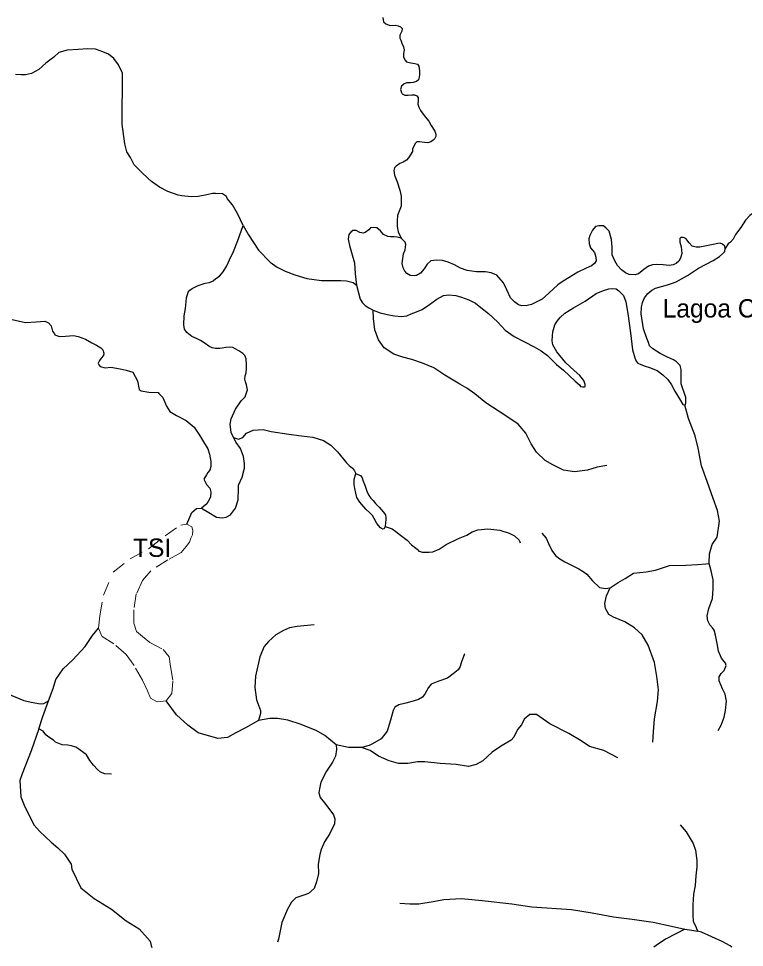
# Model space of a CAD drawing. Extents: x 436.3 to 500.4, y 8231 to 8286.4.
# Drawn here: x 489.18 to 495.5, y 8231.04 to 8239.13 of the extents above; entities that cross this region are included whole.
import ezdxf
from ezdxf.enums import TextEntityAlignment as Align

# ---------------------------------------------------------------- set-up
doc = ezdxf.new("R2010")
doc.units = 0
doc.header["$LTSCALE"] = 0.08
doc.linetypes.add('LONG_DASHED', pattern=[7.5, 6, -1.5])
doc.linetypes.add('SHORT_DASHED', pattern=[2.7, 1.5, -1.2])
for name, color, linetype, lineweight in [('2', 7, 'Continuous', 25), ('21', 7, 'SHORT_DASHED', 13), ('9', 7, 'LONG_DASHED', 25)]:
    doc.layers.add(name, color=color, linetype=linetype, lineweight=lineweight)
doc.layers.add('61', color=7, linetype='Continuous')

msp = doc.modelspace()

# ---------------------------------------------------------------- linework, layer by layer
at = {"layer": '2'}
for points in [[(495.3302, 8237.1297), (495.3276, 8237.1503), (495.3068, 8237.1684), (495.2886, 8237.1762), (495.2678, 8237.1737), (495.2262, 8237.1634), (495.1118, 8237.1405), (495.078, 8237.1405), (495.0442, 8237.1508), (495.0182, 8237.1793), (494.9897, 8237.2154), (494.9663, 8237.2258), (494.9455, 8237.2259), (494.9377, 8237.2155), (494.9376, 8237.1846), (494.948, 8237.1434), (494.9531, 8237.0866), (494.9427, 8237.0453), (494.927, 8237.0196), (494.9062, 8236.9989), (494.8777, 8236.9862), (494.8438, 8236.9811), (494.7918, 8236.9864), (494.7347, 8236.9891), (494.6983, 8236.9866), (494.6644, 8236.9763), (494.6228, 8236.9454), (494.5773, 8236.9074), (494.5488, 8236.8997), (494.4968, 8236.9024), (494.463, 8236.9179), (494.4293, 8236.9438), (494.3955, 8236.9826), (494.3696, 8237.0213), (494.3488, 8237.0755), (494.3463, 8237.1401), (494.3412, 8237.2072), (494.3205, 8237.2795), (494.2946, 8237.3053), (494.2713, 8237.326), (494.2323, 8237.3261), (494.2036, 8237.321), (494.1776, 8237.2902), (494.1542, 8237.2437), (494.1438, 8237.2128), (494.1463, 8237.1716), (494.1592, 8237.1345), (494.1929, 8237.0958), (494.2059, 8237.0545), (494.2084, 8237.021), (494.1928, 8236.9978), (494.1668, 8236.9797), (494.1225, 8236.9593), (494.0498, 8236.9232), (493.9744, 8236.877), (493.9198, 8236.8436), (493.8755, 8236.8127), (493.7975, 8236.7407), (493.7377, 8236.6892), (493.6792, 8236.6583), (493.6453, 8236.6429), (493.609, 8236.6326), (493.5622, 8236.6301), (493.5311, 8236.6379), (493.4973, 8236.6639), (493.4637, 8236.7), (493.43, 8236.7698), (493.4015, 8236.8293)], [(492.1181, 8237.2875), (492.091, 8237.286), (492.0728, 8237.2731), (492.0546, 8237.2524), (492.0494, 8237.2112), (492.0622, 8237.1544), (492.0853, 8237.0744), (492.1033, 8237.0047), (492.1109, 8236.9092), (492.1222, 8236.811)], [(492.5112, 8237.2181), (492.4749, 8237.2285), (492.4491, 8237.2311), (492.4179, 8237.2311), (492.3946, 8237.2337), (492.3557, 8237.2518), (492.3298, 8237.2828), (492.2988, 8237.3086), (492.2677, 8237.3138), (492.2443, 8237.3086), (492.2287, 8237.2907), (492.1975, 8237.2674), (492.1803, 8237.262), (492.1509, 8237.2674), (492.1181, 8237.2875)], [(493.027, 8236.9593), (492.9752, 8236.9877), (492.9207, 8237.0111), (492.8714, 8237.0241), (492.8144, 8237.0268), (492.7702, 8237.0217), (492.7364, 8236.9933), (492.7105, 8236.952), (492.6792, 8236.916), (492.6454, 8236.8953), (492.6377, 8236.8953), (492.6247, 8236.8902), (492.5884, 8236.8954), (492.5599, 8236.9109), (492.5418, 8236.9316), (492.5288, 8236.96), (492.5185, 8236.9987), (492.5264, 8237.0426), (492.5317, 8237.0839), (492.5448, 8237.1174), (492.5526, 8237.1639), (492.5449, 8237.1846), (492.5112, 8237.2181)], [(494.908, 8236.1408), (494.882, 8236.1589), (494.83, 8236.1823), (494.7651, 8236.2159), (494.7027, 8236.2548), (494.6741, 8236.2828), (494.6637, 8236.3112), (494.6455, 8236.3552), (494.6194, 8236.4311), (494.6014, 8236.5602), (494.604, 8236.617), (494.6118, 8236.6582), (494.6301, 8236.6994), (494.6587, 8236.738), (494.6925, 8236.7664), (494.7263, 8236.7843), (494.7784, 8236.7997), (494.8303, 8236.8125), (494.8642, 8236.8254), (494.9058, 8236.8381), (494.9526, 8236.8665), (495.0046, 8236.8947), (495.0986, 8236.9573), (495.2261, 8237.0242), (495.2833, 8237.0601), (495.3119, 8237.0859), (495.3275, 8237.1039), (495.3302, 8237.1297)], [(493.4015, 8236.8293), (493.3445, 8236.8964), (493.2952, 8236.9172), (493.2458, 8236.925), (493.168, 8236.9252), (493.0867, 8236.9385), (493.027, 8236.9593)], [(492.1222, 8236.811), (492.1546, 8236.6893), (492.1753, 8236.6557), (492.1986, 8236.6325), (492.2302, 8236.6135), (492.2662, 8236.5923)], [(492.2662, 8236.5923), (492.3286, 8236.5696), (492.4038, 8236.5514), (492.4531, 8236.5436), (492.5128, 8236.5384), (492.5594, 8236.5435), (492.5984, 8236.559), (492.6452, 8236.577), (492.6945, 8236.5976), (492.7569, 8236.6414), (492.8218, 8236.6878), (492.879, 8236.7187), (492.9257, 8236.7263), (492.988, 8236.7211), (493.0373, 8236.7055), (493.1002, 8236.6822), (493.1572, 8236.6537), (493.204, 8236.6149), (493.2714, 8236.5631), (493.3518, 8236.4881), (493.4166, 8236.4182), (493.4946, 8236.3639), (493.5838, 8236.3162), (493.6694, 8236.2722), (493.7292, 8236.2385), (493.7837, 8236.197), (493.8642, 8236.1195), (493.9239, 8236.0703), (494.0255, 8235.9749), (494.0619, 8235.9412), (494.0723, 8235.9283), (494.0905, 8235.9257), (494.1061, 8235.9256), (494.1139, 8235.9282), (494.1139, 8235.9437), (494.1009, 8235.9799), (494.0671, 8236.0239), (494.0177, 8236.0653), (493.9451, 8236.1326), (493.8672, 8236.2283), (493.8309, 8236.2903), (493.8257, 8236.3265), (493.8283, 8236.3677), (493.831, 8236.4039), (493.8492, 8236.4632), (493.8675, 8236.4968), (493.896, 8236.5276), (493.9352, 8236.5668), (494.0106, 8236.6131), (494.112, 8236.6697), (494.2083, 8236.7366), (494.2732, 8236.7647), (494.3174, 8236.7776), (494.3513, 8236.7801), (494.3824, 8236.7774), (494.4058, 8236.7619), (494.4473, 8236.7205), (494.4655, 8236.6663), (494.4836, 8236.563), (494.5075, 8236.3946), (494.5256, 8236.2475), (494.5437, 8236.1778), (494.5567, 8236.1493), (494.5723, 8236.1312), (494.5983, 8236.1183), (494.6346, 8236.1053), (494.6736, 8236.0923), (494.7391, 8236.0657), (494.7884, 8236.0294), (494.8326, 8235.988), (494.8638, 8235.9415), (494.8924, 8235.8872), (494.9417, 8235.8045), (494.9621, 8235.77), (494.9807, 8235.764)], [(494.9599, 8235.9162), (494.947, 8235.9497), (494.947, 8235.9781), (494.947, 8236.0246), (494.9496, 8236.0762), (494.9393, 8236.1098), (494.908, 8236.1408)], [(494.9807, 8235.764), (494.9859, 8235.7683), (494.9885, 8235.789), (494.9886, 8235.8303), (494.9755, 8235.8748), (494.9599, 8235.9162)], [(492.3715, 8234.7091), (492.3626, 8234.6884), (492.3477, 8234.6854), (492.3314, 8234.6957), (492.2987, 8234.7343), (492.2763, 8234.7772), (492.2614, 8234.8025), (492.2376, 8234.8277), (492.2035, 8234.8603), (492.1514, 8234.9196), (492.1246, 8234.9611), (492.1156, 8234.9982), (492.1082, 8235.0397), (492.1022, 8235.0738), (492.1021, 8235.1167), (492.1152, 8235.1691)], [(492.1142, 8235.1697), (492.1181, 8235.1672), (492.1571, 8235.1523), (492.1705, 8235.1331), (492.1794, 8235.1035), (492.1958, 8235.0679), (492.2121, 8235.0145), (492.2285, 8234.9775), (492.2463, 8234.9537), (492.2657, 8234.933), (492.288, 8234.9078), (492.3207, 8234.8751), (492.3549, 8234.8351), (492.3743, 8234.8099), (492.3787, 8234.7863), (492.3773, 8234.7669), (492.3744, 8234.7418), (492.3715, 8234.7091)]]:
    msp.add_lwpolyline(points, dxfattribs=at)
at = {"layer": '21'}
for points in [[(489.8759, 8233.8235), (489.8882, 8233.9299), (489.9196, 8234.1096), (490.0038, 8234.3107), (490.1516, 8234.4274), (490.31, 8234.5123), (490.4572, 8234.6269), (490.5918, 8234.7198), (490.6451, 8234.7283)], [(490.6451, 8234.7283), (490.6872, 8234.7061), (490.6985, 8234.6724), (490.6929, 8234.6359), (490.6789, 8234.605), (490.6678, 8234.5713), (490.6397, 8234.5348), (490.5955, 8234.4813), (490.4794, 8234.4176), (490.3315, 8234.3221), (490.2576, 8234.2374), (490.205, 8234.121), (490.1842, 8233.9834), (490.1844, 8233.8671), (490.2058, 8233.7932), (490.2587, 8233.751), (490.3223, 8233.6983), (490.4388, 8233.6351), (490.4918, 8233.5718), (490.5026, 8233.4872), (490.524, 8233.3603), (490.5137, 8233.2545), (490.4648, 8233.1901)], [(490.4648, 8233.1901), (490.3871, 8233.1802), (490.3284, 8233.2124), (490.3022, 8233.2752), (490.2597, 8233.3703), (490.1853, 8233.497), (490.1174, 8233.5926), (490.0085, 8233.6869), (489.9044, 8233.7528), (489.8759, 8233.8235)]]:
    msp.add_lwpolyline(points, dxfattribs=at)
at = {"layer": '9'}
msp.add_line((495.3908, 8231.043), (495.3753, 8231.0542), dxfattribs=at)
for points in [[(492.3509, 8239.142), (492.3572, 8239.1041), (492.3761, 8239.0872), (492.4162, 8239.0724), (492.4584, 8239.0744), (492.4837, 8239.0702), (492.5048, 8239.0617), (492.5196, 8239.0448), (492.5173, 8239.0217), (492.5089, 8239.0049), (492.5004, 8238.9881), (492.4982, 8238.9607), (492.5067, 8238.9438), (492.5171, 8238.9186), (492.5297, 8238.887), (492.536, 8238.8596), (492.5317, 8238.8238), (492.5316, 8238.7964), (492.5442, 8238.7712), (492.5569, 8238.7564), (492.5949, 8238.7458), (492.6286, 8238.7415), (492.6521, 8238.734), (492.6648, 8238.7172), (492.6711, 8238.6772), (492.671, 8238.6456), (492.6667, 8238.6204), (492.6624, 8238.5994), (492.6455, 8238.5846), (492.6139, 8238.5763), (492.5927, 8238.5721), (492.559, 8238.5721), (492.5357, 8238.5638), (492.5146, 8238.5449), (492.5061, 8238.5155), (492.5124, 8238.4881), (492.5208, 8238.4755), (492.5419, 8238.4649), (492.5714, 8238.4649), (492.6031, 8238.4669), (492.6263, 8238.4669), (492.6473, 8238.4585), (492.6579, 8238.4437), (492.6578, 8238.4184), (492.6557, 8238.3869), (492.664, 8238.3617), (492.6787, 8238.3301), (492.721, 8238.2766), (492.7505, 8238.2386), (492.7715, 8238.2008), (492.8031, 8238.1523), (492.8136, 8238.1251), (492.8114, 8238.1061), (492.8029, 8238.0872), (492.7881, 8238.0725)], [(491.1345, 8237.3301), (491.09, 8237.4274), (491.0415, 8237.5084), (490.9969, 8237.5651), (490.9888, 8237.5813), (490.9563, 8237.6056), (490.8953, 8237.6096), (490.8692, 8237.6077), (490.8204, 8237.5955), (490.7432, 8237.5832), (490.6821, 8237.579), (490.6008, 8237.587), (490.5683, 8237.5951), (490.4789, 8237.6273), (490.4059, 8237.6637), (490.3368, 8237.7123), (490.3085, 8237.7406), (490.2516, 8237.7933), (490.1868, 8237.8581), (490.1544, 8237.923), (490.1221, 8237.9716), (490.106, 8238.0406), (490.0822, 8238.2133), (490.0835, 8238.656), (490.0511, 8238.729), (490.0106, 8238.7858), (489.9619, 8238.8222), (489.9147, 8238.8421), (489.8493, 8238.8665), (489.7839, 8238.8685), (489.6981, 8238.8621), (489.6041, 8238.8578), (489.5304, 8238.8372), (489.4873, 8238.7964), (489.4177, 8238.7431), (489.3568, 8238.6881), (489.2932, 8238.6533), (489.24, 8238.643), (489.2012, 8238.6429), (489.1521, 8238.6448)], [(492.7881, 8238.0725), (492.7691, 8238.0578), (492.7437, 8238.0495), (492.7142, 8238.0537), (492.6695, 8238.0595), (492.6484, 8238.0575), (492.6336, 8238.0449)], [(492.6336, 8238.0449), (492.623, 8238.0239), (492.6103, 8237.9986), (492.6081, 8237.9735), (492.5742, 8237.9188), (492.5573, 8237.8978), (492.5276, 8237.881), (492.5003, 8237.8684), (492.4664, 8237.8454), (492.4516, 8237.8307), (492.4473, 8237.8076), (492.4535, 8237.7686), (492.4766, 8237.7097), (492.4997, 8237.6382), (492.5101, 8237.5857), (492.5122, 8237.5374), (492.5099, 8237.4975), (492.4993, 8237.4701), (492.4801, 8237.4176), (492.4758, 8237.3693), (492.4756, 8237.3219), (492.484, 8237.2756), (492.5112, 8237.2181)], [(496.4212, 8237.4803), (496.3951, 8237.5015), (496.3688, 8237.515), (496.3387, 8237.5228), (496.2928, 8237.5294), (496.191, 8237.5131), (496.1418, 8237.4969), (496.0991, 8237.4969), (496.0467, 8237.5002), (495.9942, 8237.5133), (495.9285, 8237.5101), (495.8597, 8237.507), (495.7707, 8237.5068), (495.7215, 8237.4971), (495.6493, 8237.481), (495.5967, 8237.4518), (495.5476, 8237.4161), (495.5082, 8237.3771), (495.4687, 8237.312), (495.4228, 8237.2503), (495.3997, 8237.2114), (495.3768, 8237.1854), (495.357, 8237.1691), (495.3302, 8237.1297)], [(491.0516, 8235.4842), (491.0296, 8235.5279), (491.0208, 8235.5979), (491.0296, 8235.646), (491.069, 8235.7292), (491.1171, 8235.8036), (491.1524, 8235.8365), (491.1611, 8235.8627), (491.1743, 8235.8977), (491.1655, 8235.9415), (491.1556, 8235.9676), (491.1496, 8235.9914), (491.1516, 8236.0211), (491.1616, 8236.047), (491.1656, 8236.0846), (491.1656, 8236.1204), (491.1617, 8236.168), (491.1498, 8236.1976), (491.1319, 8236.2155), (491.0962, 8236.2373), (491.0664, 8236.255), (491.0466, 8236.2668), (491.0188, 8236.2688), (490.985, 8236.2667), (490.9512, 8236.2608), (490.9313, 8236.2587), (490.8956, 8236.2586), (490.8657, 8236.2644), (490.8359, 8236.2783), (490.8041, 8236.302), (490.7645, 8236.3277), (490.7287, 8236.3455), (490.689, 8236.3632), (490.6454, 8236.3969), (490.6255, 8236.4265), (490.6181, 8236.4645), (490.6216, 8236.5425), (490.6319, 8236.607), (490.6388, 8236.6646), (490.6423, 8236.6985), (490.6559, 8236.7494), (490.6696, 8236.7664), (490.69, 8236.78), (490.7445, 8236.8072), (490.8056, 8236.8277), (490.843, 8236.8345), (490.8736, 8236.8482), (490.8975, 8236.8686), (490.9281, 8236.8889), (490.9621, 8236.9263), (490.9928, 8236.9773), (491.0168, 8237.0315), (491.0509, 8237.1028), (491.0885, 8237.1977), (491.1345, 8237.3301)], [(491.1345, 8237.3301), (491.1831, 8237.249), (491.2682, 8237.1153), (491.3696, 8237.0101), (491.4305, 8236.9655), (491.4995, 8236.9331), (491.5849, 8236.9007), (491.6906, 8236.8684), (491.8183, 8236.8514), (491.9851, 8236.8514), (492.0335, 8236.8478), (492.0924, 8236.8339), (492.1222, 8236.811)], [(494.3007, 8235.2397), (494.2171, 8235.2243), (494.1337, 8235.1985), (494.0189, 8235.1831), (493.925, 8235.1988), (493.8311, 8235.2456), (493.7633, 8235.2821), (493.6903, 8235.3549), (493.6433, 8235.4276), (493.5964, 8235.5211), (493.5285, 8235.5991), (493.4294, 8235.6667), (493.2469, 8235.7864), (493.153, 8235.8643), (493.0831, 8235.9118), (493.0205, 8235.9482), (492.8903, 8236.0262), (492.7965, 8236.0886), (492.6975, 8236.1302), (492.6037, 8236.1615), (492.5255, 8236.1823), (492.4474, 8236.2083), (492.3641, 8236.2654), (492.3122, 8236.3329), (492.2811, 8236.421), (492.2707, 8236.5196), (492.2662, 8236.5923)], [(489.1236, 8236.5124), (489.2156, 8236.4897), (489.2425, 8236.4859), (489.3345, 8236.49), (489.4089, 8236.4967), (489.4395, 8236.4815), (489.4625, 8236.4548), (489.474, 8236.4089), (489.4931, 8236.3861), (489.497, 8236.3784), (489.5353, 8236.3633), (489.5889, 8236.3672), (489.6579, 8236.3712), (489.7, 8236.3637), (489.7613, 8236.3409), (489.8187, 8236.3066), (489.857, 8236.2876), (489.8953, 8236.2648), (489.9144, 8236.2457), (489.9221, 8236.219), (489.9182, 8236.1961), (489.8991, 8236.173), (489.8837, 8236.1539), (489.8722, 8236.1309), (489.8799, 8236.1157), (489.8913, 8236.1004), (489.9334, 8236.089)], [(489.9334, 8236.089), (489.9833, 8236.0968), (490.0636, 8236.0818), (490.1173, 8236.0704), (490.1747, 8236.0515), (490.2142, 8235.9773), (490.2294, 8235.9009)], [(490.2294, 8235.9009), (490.2486, 8235.8895), (490.3137, 8235.8781), (490.3941, 8235.8745), (490.4018, 8235.8668), (490.4362, 8235.8325), (490.4669, 8235.7562), (490.4975, 8235.7103), (490.5549, 8235.6761), (490.6391, 8235.6304), (490.7081, 8235.5732), (490.7543, 8235.5033), (490.7888, 8235.4461), (490.8271, 8235.3849), (490.8425, 8235.3391), (490.854, 8235.274), (490.854, 8235.2319), (490.8464, 8235.1975), (490.8272, 8235.1783), (490.8158, 8235.1591), (490.7928, 8235.1208), (490.8159, 8235.0749), (490.8465, 8235.0406), (490.8542, 8235.0061), (490.8505, 8234.9639), (490.8314, 8234.9257), (490.8199, 8234.9065), (490.7712, 8234.8662)], [(495.1924, 8234.3869), (495.1961, 8234.471), (495.2176, 8234.5523), (495.2607, 8234.6164), (495.2822, 8234.7535), (495.265, 8234.8477), (495.2262, 8234.9505), (495.174, 8235.0991), (495.1266, 8235.2361), (495.0965, 8235.3902), (495.0706, 8235.4972), (495.0129, 8235.65), (494.9807, 8235.764)], [(491.0516, 8235.4842), (491.0956, 8235.4697), (491.132, 8235.4835), (491.1639, 8235.5199), (491.223, 8235.5474), (491.3095, 8235.5522), (491.3778, 8235.534), (491.5327, 8235.5116), (491.642, 8235.4981), (491.7422, 8235.4846), (491.8333, 8235.4574), (491.8972, 8235.4165), (491.9564, 8235.3574), (492.034, 8235.2619), (492.0568, 8235.2392), (492.0872, 8235.2147), (492.1036, 8235.1938), (492.1152, 8235.1691)], [(490.7712, 8234.8662), (490.8358, 8234.8299), (490.9033, 8234.7878), (490.9558, 8234.7836), (490.9865, 8234.788), (491.0259, 8234.81), (491.0696, 8234.867), (491.0914, 8234.9415), (491.0957, 8235.0378), (491.0956, 8235.0685), (491.1262, 8235.1386), (491.148, 8235.2174), (491.148, 8235.2568), (491.1392, 8235.318), (491.1129, 8235.388), (491.0734, 8235.4405), (491.0516, 8235.4842)], [(490.6451, 8234.7283), (490.687, 8234.8295), (490.7291, 8234.8633), (490.7712, 8234.8662)], [(492.3715, 8234.7091), (492.4313, 8234.6883), (492.4632, 8234.6655), (492.5043, 8234.6337), (492.5636, 8234.5882), (492.6002, 8234.5474), (492.6504, 8234.511), (492.6641, 8234.4928), (492.6961, 8234.4837), (492.7234, 8234.4837), (492.7554, 8234.4837), (492.7872, 8234.4882), (492.8419, 8234.511), (492.9012, 8234.5519), (493.0106, 8234.602), (493.0836, 8234.6338), (493.1292, 8234.6611), (493.1793, 8234.6792), (493.266, 8234.6883), (493.371, 8234.6745)], [(493.371, 8234.6745), (493.4509, 8234.6493), (493.4988, 8234.6254), (493.5371, 8234.5894), (493.5467, 8234.5655)], [(493.7352, 8234.6498), (493.7733, 8234.605), (493.7942, 8234.5601), (493.8219, 8234.4979), (493.853, 8234.4565), (493.8912, 8234.4255), (493.9363, 8234.4013), (494.0575, 8234.3391), (494.0956, 8234.3149), (494.1267, 8234.2941), (494.1753, 8234.2355), (494.2377, 8234.1768), (494.2896, 8234.1664), (494.3297, 8234.1748)], [(494.3297, 8234.1748), (494.4007, 8234.2203), (494.4615, 8234.2555), (494.5325, 8234.3018), (494.6427, 8234.3143), (494.7258, 8234.328), (494.8472, 8234.367), (494.9893, 8234.372), (495.0908, 8234.3769), (495.1619, 8234.3818), (495.1924, 8234.3869)], [(495.2709, 8232.9304), (495.2967, 8232.9775), (495.3224, 8233.0462), (495.3352, 8233.1062), (495.3437, 8233.1877), (495.3308, 8233.2478), (495.3092, 8233.2949), (495.279, 8233.3635), (495.279, 8233.3978), (495.2962, 8233.4278), (495.322, 8233.4535), (495.3391, 8233.4964), (495.3348, 8233.5179), (495.3003, 8233.5608), (495.2745, 8233.6208), (495.2615, 8233.6894), (495.2484, 8233.7623), (495.2355, 8233.8051), (495.2226, 8233.8266), (495.1967, 8233.8523), (495.1795, 8233.8867), (495.1751, 8233.9295), (495.188, 8233.9938), (495.2224, 8234.0794), (495.2266, 8234.1651), (495.2265, 8234.2438), (495.2091, 8234.321), (495.1924, 8234.3869)], [(494.7016, 8232.8292), (494.7066, 8232.9203), (494.7165, 8233.0316), (494.7417, 8233.1832), (494.7516, 8233.2844), (494.7363, 8233.4006), (494.7158, 8233.522), (494.6598, 8233.6737), (494.609, 8233.7647), (494.543, 8233.8255), (494.4568, 8233.8765), (494.3604, 8233.9171), (494.3198, 8233.9424), (494.2893, 8233.993), (494.2842, 8234.0384), (494.2993, 8234.1041), (494.3297, 8234.1748)], [(491.7526, 8233.8501), (491.6045, 8233.8356), (491.5376, 8233.826), (491.4851, 8233.802), (491.4184, 8233.7636), (491.3564, 8233.7062), (491.3183, 8233.6632), (491.2804, 8233.5723), (491.2426, 8233.405), (491.238, 8233.3046), (491.2527, 8233.1995), (491.2863, 8233.104), (491.2864, 8233.0801), (491.2693, 8233.0193)], [(489.4398, 8233.1891), (489.4824, 8233.2965), (489.5036, 8233.3752), (489.5677, 8233.4682), (489.6533, 8233.5471), (489.7603, 8233.6617), (489.8243, 8233.7591), (489.8759, 8233.8235)], [(493.0627, 8233.598), (493.0341, 8233.5215), (493.0246, 8233.4881), (493.0056, 8233.4594), (492.9627, 8233.4259), (492.9149, 8233.3878), (492.8289, 8233.3591), (492.7716, 8233.3351), (492.7478, 8233.3064), (492.7192, 8233.2539), (492.6954, 8233.2204), (492.6619, 8233.2013), (492.6143, 8233.1869), (492.5521, 8233.1678), (492.49, 8233.1533), (492.4566, 8233.1342), (492.4423, 8233.1056), (492.4187, 8233.0195), (492.3902, 8232.9239), (492.3379, 8232.8569), (492.2615, 8232.8139), (492.2329, 8232.7995), (492.1664, 8232.782)], [(488.6007, 8233.03), (488.7193, 8233.1145), (488.8148, 8233.1721), (488.8684, 8233.2028), (488.8991, 8233.2149), (488.9219, 8233.2296), (488.9525, 8233.2451), (488.9969, 8233.2605), (489.0291, 8233.2643), (489.0616, 8233.2571), (489.0866, 8233.2492), (489.2247, 8233.1921), (489.2898, 8233.177), (489.3702, 8233.1619), (489.4008, 8233.1657), (489.4398, 8233.1891)], [(489.357, 8232.9468), (489.3901, 8233.0531), (489.4398, 8233.1891)], [(491.2693, 8233.0193), (491.1543, 8232.9533), (491.0721, 8232.912), (490.9983, 8232.8706), (490.916, 8232.8623), (490.7433, 8232.9113), (490.6526, 8232.9769), (490.5537, 8233.0672), (490.4648, 8233.1901)], [(494.3982, 8232.6917), (494.2745, 8232.7575), (494.1509, 8232.7905), (494.0766, 8232.8398), (493.9694, 8232.9056), (493.8045, 8232.9879), (493.689, 8233.0702), (493.6314, 8233.0702), (493.582, 8233.0291), (493.5575, 8232.9796), (493.5246, 8232.9386), (493.4918, 8232.8728), (493.4671, 8232.848), (493.3767, 8232.7905), (493.3027, 8232.741), (493.2205, 8232.667), (493.163, 8232.634), (493.0971, 8232.6176), (492.9901, 8232.6339), (492.8502, 8232.6421), (492.7179, 8232.6591), (492.6521, 8232.659), (492.5699, 8232.6425), (492.4876, 8232.6424), (492.4052, 8232.6671), (492.3146, 8232.7081), (492.2405, 8232.7574), (492.1664, 8232.782)], [(491.9442, 8232.8064), (491.8453, 8232.8886), (491.7711, 8232.9296), (491.6312, 8232.987), (491.5242, 8233.0198), (491.4337, 8233.0361), (491.3679, 8233.036), (491.2693, 8233.0193)], [(489.357, 8232.9468), (489.2908, 8232.7526), (489.2127, 8232.5522), (489.1914, 8232.495), (489.199, 8232.3519), (489.2277, 8232.2806), (489.314, 8232.1091), (489.3642, 8232.0521), (489.4645, 8231.9593), (489.5219, 8231.9094), (489.5792, 8231.8523), (489.6366, 8231.7666), (489.6438, 8231.7238), (489.7228, 8231.5594), (489.8374, 8231.4667), (489.9877, 8231.3741), (490.1166, 8231.2741), (490.2312, 8231.2029), (490.3242, 8231.0958)], [(489.9895, 8232.5502), (489.932, 8232.5539), (489.8938, 8232.5692), (489.8669, 8232.592), (489.8324, 8232.6303), (489.8017, 8232.6685), (489.7709, 8232.7181), (489.7479, 8232.7372), (489.7057, 8232.7677), (489.6789, 8232.7869), (489.6406, 8232.7982), (489.61, 8232.802), (489.5603, 8232.8056), (489.5027, 8232.8285), (489.4836, 8232.8476), (489.4337, 8232.8781), (489.4183, 8232.8933), (489.3953, 8232.9239), (489.357, 8232.9468)], [(491.9442, 8232.8064), (491.9485, 8232.7656), (491.9388, 8232.7066), (491.9128, 8232.6542), (491.8608, 8232.577), (491.8121, 8232.4821), (491.7992, 8232.4233), (491.7927, 8232.3873), (491.8058, 8232.348), (491.8551, 8232.286), (491.9206, 8232.1977), (491.9338, 8232.1617), (491.9307, 8232.1192), (491.8884, 8232.0329), (491.8429, 8231.9609), (491.8136, 8231.8954), (491.804, 8231.8496), (491.7878, 8231.7678), (491.7913, 8231.6859), (491.7751, 8231.614), (491.7525, 8231.5551), (491.7035, 8231.5124), (491.6643, 8231.4961), (491.5925, 8231.473), (491.5566, 8231.4369), (491.5202, 8231.3735), (491.4712, 8231.2582), (491.4435, 8231.1131), (491.4347, 8231.0873)], [(492.1664, 8232.782), (492.0512, 8232.7819), (491.9442, 8232.8064)], [(494.9388, 8232.1093), (494.993, 8232.0469), (495.0516, 8231.9471), (495.0725, 8231.8889), (495.0852, 8231.7974), (495.0854, 8231.7432), (495.0773, 8231.6642), (495.0692, 8231.581), (495.0569, 8231.5043), (495.0487, 8231.4128), (495.049, 8231.3211), (495.0533, 8231.2713), (495.0781, 8231.2143), (495.0906, 8231.1824)], [(492.4995, 8231.4283), (492.5868, 8231.4201), (492.6658, 8231.4202), (492.7906, 8231.4411), (492.882, 8231.4578), (493.0359, 8231.4662), (493.2149, 8231.4498), (493.4729, 8231.4207), (493.6477, 8231.3958), (493.9933, 8231.371), (494.1723, 8231.3418), (494.3598, 8231.3086), (494.5222, 8231.2878), (494.7056, 8231.2627), (494.864, 8231.2252), (494.979, 8231.2001)], [(494.979, 8231.2001), (494.9083, 8231.1627), (494.8126, 8231.1129), (494.7295, 8231.0587), (494.7098, 8231.0428)], [(494.979, 8231.2001), (495.0416, 8231.1903), (495.0906, 8231.1824)], [(495.3753, 8231.0542), (495.3044, 8231.0917), (495.1247, 8231.1755), (495.0906, 8231.1824)], [(490.3242, 8231.0958), (490.3345, 8231.0583), (490.3397, 8231.0414)]]:
    msp.add_lwpolyline(points, dxfattribs=at)

# ---------------------------------------------------------------- texts
at = {"layer": '61'}
msp.add_text('Lagoa Comprida', height=0.16, dxfattribs=at).set_placement((494.7874, 8236.5283))
msp.add_text('TSI', height=0.16, dxfattribs=at).set_placement((490.3429, 8234.4432), align=Align.CENTER)

doc.saveas('drawing.dxf')
